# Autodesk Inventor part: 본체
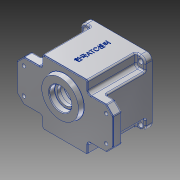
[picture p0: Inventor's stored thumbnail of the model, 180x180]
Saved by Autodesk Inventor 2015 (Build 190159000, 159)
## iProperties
Created: 2016-02
Part Number: 본체
Material: Aluminum 6061
Document SubType Name: Modeling
Designer: Administrator
Density: 2.7 g/cm^3
Appearance: Aluminum - Flat
Mass: 874.188 g
Surface Area: 763.073 cm^2
Volume: 323.773 cm^3
Author: Administrator
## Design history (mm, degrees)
sketch "Sketch1"
  geometry: L1 (-70, -30)-(70, -30); L2 (70, -30)-(70, 30); L3 (70, 30)-(-70, 30); L4 (-70, 30)-(-70, -30); L5 (-70, -30)-(70, 30); L6 (70, -30)-(-70, 30); 1 further point
  constraints: 12 end point, 2 midpoint, 2 parallel, 1 horizontal, 1 perpendicular
  dimensions: "d0" = 140 distance of L3.end L2.end; "d1" = 60 distance of L2.end L1.end
extrude "Extrusion1" new body sketch "Sketch1" distance "d2" = 13; taper "d3" = 0 deg
sketch "Sketch2"
  geometry: L1 (-33, -47)-(33, -47); L2 (33, -47)-(33, 47); L3 (33, 47)-(-33, 47); L4 (-33, 47)-(-33, -47); L5 (-33, -47)-(33, 47); L6 (33, -47)-(-33, 47); 1 further point
  constraints: 12 end point, 2 midpoint, 2 parallel, 1 horizontal, 1 perpendicular
  dimensions: "d4" = 66 distance of L3.end L2.end; "d5" = 94 distance of L2.end L1.end
extrude "Extrusion2" join sketch "Sketch2" distance "d6" = 80; taper "d7" = 0 deg
sketch "Sketch3"
  geometry: L1 (-47, 47)-(47, 47); L2 (47, 47)-(47, -47); L3 (47, -47)-(-47, -47); L4 (-47, -47)-(-47, 47); L5 (-47, 47)-(47, -47); L6 (47, 47)-(-47, -47); 1 further point
  constraints: 12 end point, 2 midpoint, 2 parallel, 1 horizontal, 1 perpendicular
  dimensions: "d8" = 94 distance of L2.end L3.end; "d9" = 94 distance of L1.end L2.end
extrude "Extrusion3" join sketch "Sketch3" distance "d10" = 10; taper "d11" = 0 deg
sketch "Sketch4"
  geometry: L1 (-47, 30)-(47, 30); L2 (47, 30)-(47, -30); L3 (47, -30)-(-47, -30); L4 (-47, -30)-(-47, 30); L5 (-47, 30)-(47, -30); L6 (47, 30)-(-47, -30); 1 further point
  constraints: 12 end point, 2 midpoint, 2 parallel, 1 horizontal, 1 perpendicular
  dimensions: "d12" = 60 distance of L1.end L2.end; "d13" = 94 distance of L2.end L3.end
extrude "Extrusion4" join sketch "Sketch4" stored distance "d14" = 10; taper "d15" = 0 deg
sketch "Sketch5"
  geometry: C1 r 43 at (0, 0); 1 further point
  constraints: 1 centre point, 1 coincident
  dimensions: "d16" = 86 diameter of C1
extrude "Extrusion5" cut sketch "Sketch5" distance "d17" = 9; taper "d18" = 0 deg
sketch "Sketch6"
  geometry: C1 r 43 at (0, 0) reference; C2 r 40 at (0, 0); 1 further point
  constraints: 1 centre point, 1 coincident
  dimensions: "d19" = 80 diameter of C2
extrude "Extrusion6" cut sketch "Sketch6" distance "d20" = 62; taper "d21" = 0 deg
sketch "Sketch7"
  geometry: L1 (36, 0)-(-36, 0); L2 (39.799, -4)-(35.777, -4); L3 (39.799, 4)-(35.777, 4); L4 (-35.777, -4)-(-39.799, -4); L5 (-35.777, 4)-(-39.799, 4); A1 r 40 centre (0, 0) between (-39.799, -4) and (-39.799, 4) reference; A2 r 36 centre (0, 0) between (36, 0) and (-36, 0); A3 r 4 centre (36, 0) between (36, 4) and (36, -4); A4 r 4 centre (-36, 0) between (-36, -4) and (-36, 4); 4 further points
  constraints: 14 point on circle, 10 end point, 6 coincident, 5 horizontal, 4 point on line, 4 tangent, 3 centre point, 1 midpoint
  dimensions: "d22" = 72 diameter of A2; "d23" = 8 diameter of A3; "d24" = 8 diameter of A4
extrude "Extrusion7" join sketch "Sketch7" stored distance "d25" = 62; taper "d26" = 0 deg
fillet "Fillet1" dims "d27" = 3.5
hole "Hole1" sketch "Sketch7" diameter "d28" = 3.242; stored, may be unused: countersink angle "d32" = 90 deg, drill point angle "d34" = 118 deg; dims "d29" = 7, "d30" = 4, "d31" = 2, "d33" = 9
sketch "Sketch8"
  geometry: C1 r 28 at (0, 11); 1 further point
  constraints: 1 centre point, 1 vertical alignment
  dimensions: "d35" = 56 diameter of C1; "d36" = 11 distance of point (0, 0) C1.centre
extrude "Extrusion8" join sketch "Sketch8" distance "d37" = 7; taper "d38" = -10 deg
hole "Hole2" diameter "d41" = 25; stored, may be unused: countersink angle "d45" = 90 deg, drill point angle "d47" = 0 deg; dims "d39" = 10, "d40" = 10, "d42" = 7, "d43" = 32, "d44" = 8, "d46" = 13
sketch "Sketch9"
  geometry: A1 r 21 centre (0, -11) between (-8.978, 7.984) and (8.978, 7.984); A2 r 15 centre (0, 20) between (8.978, 7.984) and (-8.978, 7.984); 1 further point
  constraints: 4 point on circle, 2 centre point, 2 vertical alignment
  dimensions: "d48" = 42 diameter of A1; "d49" = 11 distance of A1.centre point (0, 0); "d50" = 30 diameter of A2; "d51" = 20 distance of A2.centre point (0, 0)
extrude "Extrusion9" join sketch "Sketch9" distance "d52" = 7; taper "d53" = 0 deg
fillet "Fillet2" dims "d54" = 3
hole "Hole3" diameter "d57" = 19; stored, may be unused: countersink angle "d61" = 90 deg, drill point angle "d63" = 0 deg; dims "d55" = 10, "d56" = 10, "d58" = 7, "d59" = 22, "d60" = 7, "d62" = 8
hole "Hole4" diameter "d66" = 25; stored, may be unused: countersink angle "d70" = 90 deg, drill point angle "d72" = 0 deg; dims "d64" = 10, "d65" = 10, "d67" = 7, "d68" = 35, "d69" = 10, "d71" = 15
chamfer "Chamfer1" distance "d73" = 1; stored, may be unused: second distance "d74" = 2, angle "d75" = 45 deg
sketch "Sketch10"
  geometry: L1 (47, 47)-(47, -47) reference; L2 (-47, 47)-(47, 47) reference; L3 (-47, -47)-(-47, 47) reference; L4 (47, -47)-(-47, -47) reference; L5 (-40, 40)-(40, 40); L6 (40, 40)-(40, -40); L7 (40, -40)-(-40, -40); L8 (-40, -40)-(-40, 40); L9 (-40, 40)-(40, -40); L10 (40, 40)-(-40, -40); C1 r 43 at (0, 0) reference; 5 further points
  constraints: 12 end point, 4 coincident, 2 midpoint, 2 parallel, 1 horizontal, 1 perpendicular
  dimensions: "d76" = 80 distance of L6.end L7.end; "d77" = 80 distance of L5.end L6.end
hole "Hole5" sketch "Sketch10" at (40, -40), (40, 40), (-40, 40), (-40, -40) diameter "d78" = 7; stored, may be unused: countersink angle "d82" = 90 deg, drill point angle "d84" = 0 deg; dims "d79" = 7, "d80" = 35, "d81" = 10, "d83" = 15
workplane "Work Plane1"
sketch "Sketch13"
  geometry: L1 (70, 30)-(33, 30) reference; L2 (70, -30)-(70, 30) reference; L3 (33, -30)-(70, -30) reference; L4 (33, -30)-(33, -47) reference; L5 (33, -47)-(-33, -47) reference; L6 (-33, -47)-(-33, -30) reference; L7 (-70, -30)-(-33, -30) reference; L8 (-70, 30)-(-70, -30) reference; L9 (-33, 30)-(-70, 30) reference; L10 (-33, 30)-(-33, 47) reference; L11 (-33, 47)-(33, 47) reference; L12 (33, 47)-(33, 30) reference; L13 (-60, -19)-(60, -19); L14 (60, -19)-(60, 19); L15 (60, 19)-(-60, 19); L16 (-60, 19)-(-60, -19); L17 (-60, -19)-(60, 19); L18 (60, -19)-(-60, 19); C1 r 28 at (0, 11) reference; 5 further points
  constraints: 12 end point, 4 coincident, 2 midpoint, 2 parallel, 1 horizontal, 1 perpendicular
  dimensions: "d88" = 120 distance of L15.end L14.end; "d89" = 38 distance of L14.end L13.end
hole "Hole6" sketch "Sketch13" at (60, -19), (60, 19), (-60, -19), (-60, 19) diameter "d90" = 5; stored, may be unused: countersink angle "d94" = 90 deg, drill point angle "d96" = 0 deg; dims "d91" = 7, "d92" = 9, "d93" = 4, "d95" = 15
fillet "Fillet3" dims "d97" = 0.3
chamfer "Chamfer2" distance "d98" = 10; stored, may be unused: second distance "d99" = 2, angle "d100" = 45 deg
fillet "Fillet4" dims "d101" = 8
sketch "Sketch14"
  geometry: L1 (70, -20)-(60, -30) reference; L2 (70, 20)-(70, -20) reference; L3 (60, 30)-(70, 20) reference; L4 (33, 30)-(60, 30) reference; L5 (33, 30)-(33, 47) reference; L6 (33, 47)-(-33, 47) reference; L7 (-33, 47)-(-33, 30) reference; L8 (-60, 30)-(-33, 30) reference; L9 (-70, 20)-(-60, 30) reference; L10 (-70, -20)-(-70, 20) reference; L11 (-60, -30)-(-70, -20) reference; L12 (-33, -30)-(-60, -30) reference; L13 (-33, -30)-(-33, -47) reference; L14 (-33, -47)-(33, -47) reference; L15 (33, -47)-(33, -30) reference; L16 (60, -30)-(33, -30) reference; L17 (32, -29)-(32, -46); L18 (32, -46)-(-32, -46); L19 (-32, -46)-(-32, -29); L20 (-32, -29)-(-59.586, -29); L21 (-59.586, -29)-(-69, -19.586); L22 (-69, -19.586)-(-69, 19.586); L23 (-69, 19.586)-(-59.586, 29); L24 (-59.586, 29)-(-32, 29); L25 (-32, 29)-(-32, 46); L26 (-32, 46)-(32, 46); L27 (32, 46)-(32, 29); L28 (32, 29)-(59.586, 29); L29 (59.586, 29)-(69, 19.586); L30 (69, 19.586)-(69, -19.586); L31 (69, -19.586)-(59.586, -29); L32 (59.586, -29)-(32, -29); C1 r 2.5 at (60, -19) reference; C2 r 2.5 at (-60, -19) reference; C3 r 2.5 at (-60, 19) reference; C4 r 2.5 at (60, 19) reference; C5 r 28 at (0, 11) reference; 1 further point
  constraints: 32 end point, 15 other
  dimensions: "d102" = 1 distance between parallel lines of L16 L32
extrude "Extrusion10" cut sketch "Sketch14" distance "d103" = 1; taper "d104" = 0 deg
fillet "Fillet8" dims "d108" = 5
fillet "Fillet9" dims "d109" = 5
fillet "Fillet10" dims "d110" = 2
fillet "Fillet11" dims "d111" = 2
fillet "Fillet13" dims "d113" = 2
fillet "Fillet14" dims "d114" = 2
fillet "Fillet15" dims "d115" = 2
fillet "Fillet16" dims "d116" = 2
fillet "Fillet17" dims "d117" = 2
fillet "Fillet18" dims "d118" = 2
sketch "Sketch15"
  geometry: L1 (78, 0)-(0, 0) reference; 2 further points
  constraints: 1 vertical alignment, 1 other
  dimensions: "d119" = 40 distance from line of L1 point (39, -40)
emboss "Emboss1" sketch "Sketch15" dims "d8" = 94, "d9" = 94, "d120" = 0.5, "d121" = 0
fillet "Fillet19" dims "d122" = 2
fillet "Fillet20" dims "d123" = 0.3
fillet "Fillet21" dims "d124" = 2
body "Solid1"
node "Projected Loop1"
node "Projected Loop2"
node "Projected Loop4"
node "Projected Loop5"
other parameters: "d87" = 13
